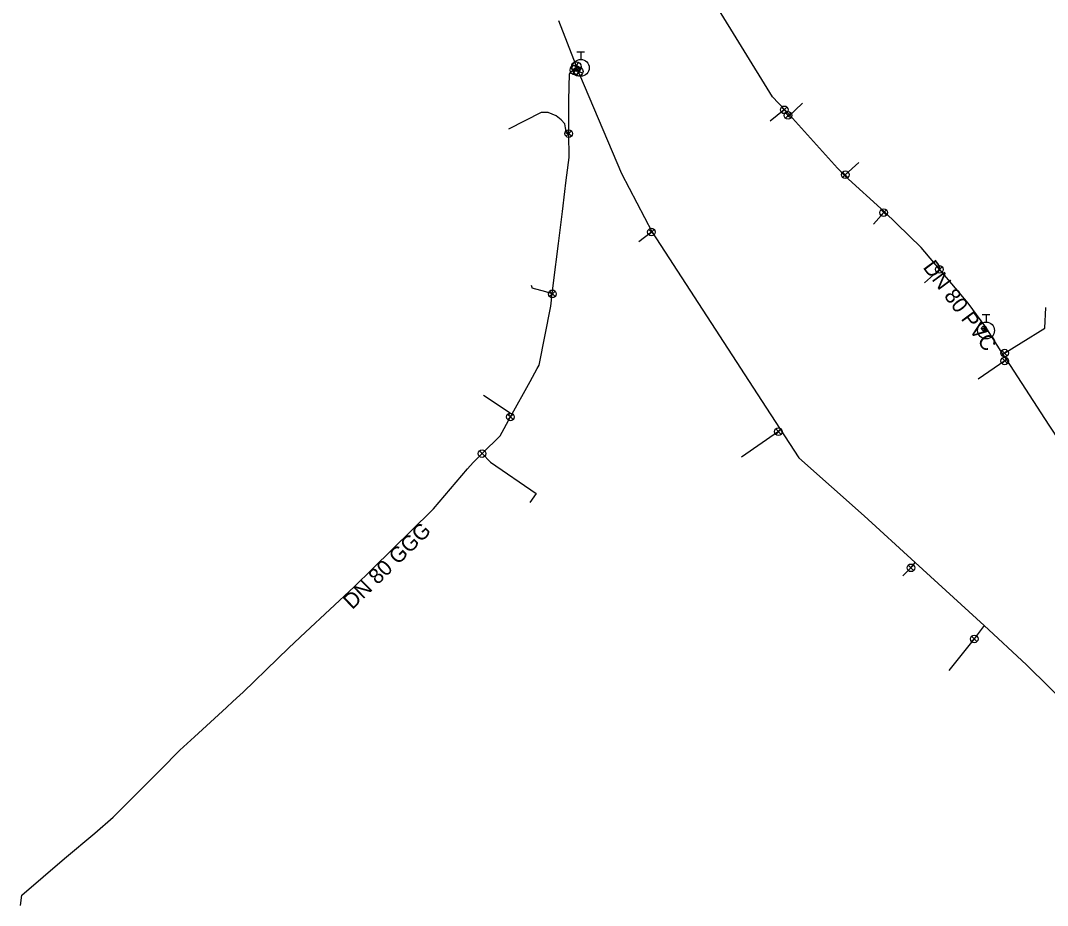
# Model space of a CAD drawing. Extents: x -484785 to -484462, y -1128039 to -1127627.
# Drawn here: x -484753.6 to -484646.3, y -1127810.7 to -1127718.2 of the extents above; entities that cross this region are included whole.
import ezdxf

# ---------------------------------------------------------------- set-up
doc = ezdxf.new("R2010")
doc.units = 0
for name, color, linetype in [('_hydrantova_odbocka_', 7, 'Continuous'), ('_pripojka_prevzato_z_dokumentace_', 7, 'Continuous'), ('_pripojka_priblizne_', 7, 'Continuous'), ('_voda_smvak_prevzato_z_dokumentace_', 7, 'Continuous'), ('Default', 7, 'Continuous'), ('MoLevel 27', 7, 'Continuous'), ('MoLevel 28', 7, 'Continuous'), ('MoLevel 46', 7, 'Continuous'), ('MoLevel 53', 7, 'Continuous')]:
    doc.layers.add(name, color=color, linetype=linetype)

# ---------------------------------------------------------------- blocks, each defined once
blk = doc.blocks.new('_uzaver_')
at = {"layer": 'Default'}
for p, q in [((-0.000035, -0.000035), (0.000035, 0.000035)), ((0.000035, -0.000035), (-0.000035, 0.000035))]:
    blk.add_line(p, q, dxfattribs=at)
for radius in [0.00005, 0.0000025]:
    blk.add_circle((0, 0), radius, dxfattribs=at)
blk = doc.blocks.new('_uzaver_pripojka_')
at = {"layer": 'Default'}
for p, q in [((-0.000035, -0.000035), (0.000035, 0.000035)), ((0.000035, -0.000035), (-0.000035, 0.000035))]:
    blk.add_line(p, q, dxfattribs=at)
for radius in [0.00005, 0.0000025]:
    blk.add_circle((0, 0), radius, dxfattribs=at)
blk = doc.blocks.new('_hydrant_voda_')
at = {"layer": 'Default'}
for p, q in [((-0.0000225, 0.000095), (0.0000225, 0.000095)), ((0, 0.000095), (0, 0.00005))]:
    blk.add_line(p, q, dxfattribs=at)
blk.add_circle((0, 0), 0.00005, dxfattribs=at)

msp = doc.modelspace()

# ---------------------------------------------------------------- linework, layer by layer
at = {"layer": '_hydrantova_odbocka_'}
msp.add_line((-484695.43, -1127723.33), (-484695.07, -1127723.19), dxfattribs=at)
msp.add_lwpolyline([(-484652.74, -1127750.29), (-484652.91, -1127750.43), (-484652.7, -1127750.64)], dxfattribs=at)
at = {"layer": '_pripojka_prevzato_z_dokumentace_'}
for p, q in [((-484699.19, -1127727.86), (-484702.63, -1127729.59)), ((-484659.14, -1127745.67), (-484657.58, -1127744.26)), ((-484705.38, -1127763.5), (-484704.49, -1127764.39))]:
    msp.add_line(p, q, dxfattribs=at)
for points in [[(-484673.29, -1127728.06), (-484673.4, -1127728.16), (-484673.47, -1127728.22), (-484673.38, -1127728.31), (-484671.88, -1127726.88)], [(-484696.32, -1127730.06), (-484696.57, -1127730.06), (-484696.66, -1127729.46), (-484696.72, -1127729.04), (-484697.1, -1127728.62), (-484697.63, -1127728.19), (-484698.49, -1127727.87), (-484699.19, -1127727.86)], [(-484673.76, -1127727.55), (-484673.8, -1127727.58), (-484675.26, -1127728.75)], [(-484667.45, -1127734.47), (-484667.42, -1127734.36), (-484665.99, -1127733.1)], [(-484663.3, -1127738.25), (-484663.4, -1127738.32), (-484664.48, -1127739.54)], [(-484687.62, -1127740.36), (-484687.68, -1127740.36), (-484689, -1127741.37)], [(-484698.04, -1127746.81), (-484698.72, -1127746.61), (-484700.13, -1127746.2)], [(-484649.04, -1127751.92), (-484646.57, -1127750.38), (-484646.44, -1127748.22)], [(-484650.95, -1127753.11), (-484650.76, -1127753), (-484649.04, -1127751.92)], [(-484650.61, -1127753.6), (-484650.75, -1127753.82), (-484653.53, -1127755.74)], [(-484702.42, -1127759.67), (-484702.63, -1127759.47), (-484702.45, -1127759.28)], [(-484674.21, -1127760.95), (-484674.41, -1127761.21), (-484678.28, -1127763.87)], [(-484661.39, -1127776.29), (-484660.56, -1127775.44), (-484660.1, -1127774.89)], [(-484652.89, -1127781.48), (-484653.94, -1127782.87), (-484656.59, -1127786.17)]]:
    msp.add_lwpolyline(points, dxfattribs=at)
at = {"layer": '_pripojka_priblizne_'}
for p, q in [((-484700.25, -1127745.89), (-484700.13, -1127746.2)), ((-484702.45, -1127759.28), (-484705.25, -1127757.44))]:
    msp.add_line(p, q, dxfattribs=at)
msp.add_lwpolyline([(-484704.49, -1127764.39), (-484699.74, -1127767.67), (-484700.4, -1127768.63)], dxfattribs=at)
at = {"layer": '_voda_smvak_prevzato_z_dokumentace_'}
for p, q in [((-484697.4, -1127718.25), (-484695.6, -1127722.9)), ((-484695.68, -1127723.42), (-484695.43, -1127723.33)), ((-484695.6, -1127722.9), (-484695.53, -1127723.07)), ((-484695.53, -1127723.07), (-484695.43, -1127723.33)), ((-484695.43, -1127723.33), (-484695.33, -1127723.57)), ((-484695.33, -1127723.57), (-484695.29, -1127723.68))]:
    msp.add_line(p, q, dxfattribs=at)
for points in [[(-484643.08, -1127765.34), (-484645.56, -1127761.38), (-484646.12, -1127760.52), (-484650.61, -1127753.6), (-484650.95, -1127753.11), (-484652.74, -1127750.29), (-484654.58, -1127747.8), (-484659.5, -1127741.98), (-484663.3, -1127738.25), (-484667.45, -1127734.47), (-484668.22, -1127733.67), (-484673.26, -1127728.1), (-484673.76, -1127727.55), (-484675.04, -1127726.21), (-484681.24, -1127716.17), (-484682.76, -1127712.65), (-484683.58, -1127711.28), (-484684.33, -1127709.73), (-484687.86, -1127701.92), (-484687.92, -1127701.76), (-484691.71, -1127695.75), (-484698.39, -1127690.88), (-484712.1, -1127682.86)], [(-484753.63, -1127810.72), (-484753.49, -1127809.65), (-484749.05, -1127805.83), (-484745.88, -1127803.15), (-484743.94, -1127801.51), (-484741.13, -1127798.68), (-484738.63, -1127796.15), (-484737.36, -1127794.86), (-484736.99, -1127794.49), (-484735.44, -1127793.09), (-484732.11, -1127790.03), (-484731.44, -1127789.41), (-484730.69, -1127788.73), (-484730.37, -1127788.43), (-484729.17, -1127787.28), (-484727.96, -1127786.11), (-484725.57, -1127783.81), (-484723.85, -1127782.16), (-484718.77, -1127777.44), (-484716.84, -1127775.54), (-484710.63, -1127769.45), (-484710.47, -1127769.29), (-484706.89, -1127765.1), (-484706.32, -1127764.44), (-484705.38, -1127763.5), (-484703.5, -1127761.63), (-484702.42, -1127759.67), (-484700.36, -1127755.96), (-484699.62, -1127754.62), (-484699.43, -1127754.27), (-484698.2, -1127748.09), (-484698.04, -1127746.81), (-484697.9, -1127745.66), (-484697.4, -1127741.54), (-484696.99, -1127738.22), (-484696.73, -1127736.11), (-484696.62, -1127735.22), (-484696.35, -1127733.09), (-484696.29, -1127732.57), (-484696.32, -1127730.06), (-484696.33, -1127729.44), (-484696.31, -1127726.58), (-484696.24, -1127723.81), (-484696.09, -1127723.58), (-484695.68, -1127723.42)], [(-484695.29, -1127723.68), (-484695.19, -1127723.9), (-484690.81, -1127734.23), (-484687.62, -1127740.36), (-484676.16, -1127757.95), (-484674.21, -1127760.95), (-484672.26, -1127763.95), (-484665.44, -1127770.01), (-484660.1, -1127774.89), (-484652.89, -1127781.48), (-484648.49, -1127785.58), (-484632.11, -1127801.7)]]:
    msp.add_lwpolyline(points, dxfattribs=at)

# ---------------------------------------------------------------- block references
at = {"layer": 'MoLevel 27'}
for p, xscale, yscale, rotation in [((-484695.68, -1127723.42), 10000, 9999.999999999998, -158.682088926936), ((-484695.53, -1127723.07), 10000, 10000.000000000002, -68.96248915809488), ((-484695.33, -1127723.57), 10000, 10000, 112.61986495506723), ((-484652.91, -1127750.43), 5000, 5000, -45.00000001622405)]:
    msp.add_blockref('_uzaver_', p, dxfattribs=dict(at, xscale=xscale, yscale=yscale, rotation=rotation))
at = {"layer": 'MoLevel 28', "xscale": 17636.68430335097, "yscale": 17636.68430335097}
for p in [(-484695.07, -1127723.19), (-484652.7, -1127750.64)]:
    msp.add_blockref('_hydrant_voda_', p, dxfattribs=at)
at = {"layer": 'MoLevel 53', "xscale": 7999.999999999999, "yscale": 7999.999999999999}
for p in [(-484673.8, -1127727.58), (-484673.4, -1127728.16), (-484696.32, -1127730.06), (-484667.42, -1127734.36), (-484663.4, -1127738.32), (-484687.68, -1127740.36), (-484657.58, -1127744.26), (-484698.04, -1127746.81), (-484650.76, -1127753), (-484650.75, -1127753.82), (-484702.42, -1127759.67), (-484674.41, -1127761.21), (-484705.38, -1127763.5), (-484660.56, -1127775.44), (-484653.94, -1127782.87)]:
    msp.add_blockref('_uzaver_pripojka_', p, dxfattribs=at)

# ---------------------------------------------------------------- texts
at = {"layer": 'MoLevel 46'}
for s, rotation, p in [('DN 80 PVC', 306.5101, (-484659.36, -1127744.05)), ('DN 80 GGG', 44.441, (-484718.95, -1127779.86))]:
    msp.add_text(s, height=1.605, rotation=rotation, dxfattribs=at).set_placement(p)

doc.saveas('drawing.dxf')
